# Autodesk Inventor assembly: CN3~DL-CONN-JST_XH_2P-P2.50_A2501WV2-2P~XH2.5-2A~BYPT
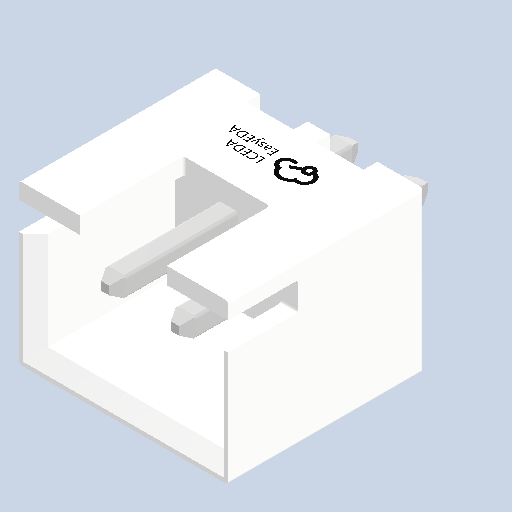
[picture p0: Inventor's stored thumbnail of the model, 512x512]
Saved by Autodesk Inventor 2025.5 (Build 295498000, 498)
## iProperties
Created: 2026-10
Part Number: CN3~DL-CONN-JST_XH_2P-P2.50_A2501WV2-2P~XH2.5-2A~BYPT
Document SubType Name: Assembly
Designer: Luis M
Author: Luis M
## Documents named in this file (2)
- C:\Users\Luis M\Downloads\3D_PCB1_2026-10-28\CN3~DL-CONN-JST_XH_2P-P2.50_A2501WV2-2P~XH2.5-2A~BYPT.iam
- C:\Users\Luis M\Downloads\3D_PCB1_2026-10-28\DL-CONN-JST_XH_2P-P2.50_A2501WV2-2P~XH2.5-2A~i7Qw.ipt
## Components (1 placed, 1 different names)
1. CN3->0
